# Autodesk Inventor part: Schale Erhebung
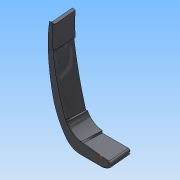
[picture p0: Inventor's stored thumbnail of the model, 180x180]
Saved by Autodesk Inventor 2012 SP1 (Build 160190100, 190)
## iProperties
Created: 2012-02
Part Number: Schale Erhebung
Material: S235JR+N ; 1.0116
Document SubType Name: Modeling
Designer: HUS
Density: 7.85 g/cm^3
Author: HUS
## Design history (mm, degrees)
workplane "Arbeitsebene1"
sketch "Skizze15"
  geometry: L1 (0, 112460.081)-(0, -18764.062) reference; L2 (-7625.161, 0)-(33492.439, 0) reference; L3 (233.258, 0)-(0, 0); L4 (-59.793, 88.26)-(221.355, 120.824); A1 r 97611.323 centre (27618.496, 93713.775) between (-29.671, 99.945) and (-29.671, 99.945); A2 r 1092.429 centre (-510.057, 901.526) between (582.372, 902.855) and (565.345, 1093.654); A3 r 72.871 centre (564.126, 1020.793) between (565.345, 1093.654) and (534.585, 1087.408); A4 r 2333.592 centre (-1751.218, 900.016) between (525.168, 386.483) and (582.372, 902.855); A5 r 2202.735 centre (-1667.311, 1026.612) between (397.261, 258.767) and (534.585, 1087.408); A6 r 276.67 centre (137.046, 355.352) between (379.784, 222.596) and (381.8, 226.351); A7 r 830.227 centre (-284.708, 569.184) between (382.626, 75.278) and (525.168, 386.483); A8 r 213.94 centre (196.739, 333.344) between (221.355, 120.824) and (397.261, 258.767); A9 r 185.828 centre (233.258, 185.828) between (233.258, 0) and (382.626, 75.278); A10 r 30 centre (-56.341, 58.459) between (-59.793, 88.26) and (-80.488, 40.656); A11 r 100 centre (0, 100) between (-80.488, 40.656) and (0, 0)
  constraints: 23 point on circle, 11 centre point, 9 tangent, 4 end point, 1 horizontal
  dimensions: "d197" = 100 radius of A11; "d198" = 30 radius of A10
sketch "Skizze16"
  geometry: L1 (233.259, 0)-(0, 0); L2 (-65.624, 24.545)-(-53.83, 36.782); L3 (-45.086, 70.419)-(238.074, 70.419); L4 (238.074, 70.419)-(238.074, 95.092); L5 (398.936, 202.433)-(418.507, 199.342); L6 (549.625, 827.221)-(534.585, 829.597); L7 (0, 0)-(233.259, 0); A1 r 1092.429 centre (-510.056, 901.526) between (582.372, 902.855) and (565.345, 1093.654); A2 r 72.871 centre (564.126, 1020.793) between (565.345, 1093.654) and (534.585, 1087.408); A3 r 17.417 centre (-48.326, 53.306) between (-45.086, 70.419) and (-53.83, 36.782); A4 r 194.102 centre (225.088, 288.759) between (238.074, 95.092) and (398.936, 202.433); A5 r 4086.087 centre (-3503.399, 1345.971) between (418.507, 199.342) and (549.625, 827.221); A6 r 2237.23 centre (-1698.928, 958.502) between (534.585, 829.597) and (534.585, 1087.408); A7 r 72.871 centre (564.126, 1020.793) between (549.625, 1092.207) and (534.585, 1087.408); A8 r 72.871 centre (564.126, 1020.793) between (565.345, 1093.654) and (549.625, 1092.207); A9 r 1092.429 centre (-510.056, 901.526) between (582.372, 902.855) and (565.345, 1093.654); A10 r 2333.592 centre (-1751.218, 900.016) between (525.168, 386.483) and (582.372, 902.855); A11 r 100 centre (0, 100) between (-65.624, 24.545) and (0, 0); A12 r 830.227 centre (-284.707, 569.184) between (382.627, 75.278) and (525.168, 386.483); A13 r 830.227 centre (-284.707, 569.184) between (382.627, 75.278) and (525.168, 386.483); A14 r 185.828 centre (233.258, 185.828) between (233.259, 0) and (382.627, 75.278)
  constraints: 29 point on circle, 14 centre point, 14 end point, 2 concentric, 2 parallel, 2 perpendicular, 2 tangent
workpoint "Arbeitspunkt2"
sketch "Skizze19"
  geometry: L1 (-39.856, 70.419)-(-250, 70.419); A1 r 44.453 centre (-39.856, 114.872) between (-39.856, 70.419) and (0, 95.186); 1 further point
  constraints: 2 end point, 2 point on circle, 1 centre point, 1 coincident, 1 horizontal, 1 tangent
feature "Erhebung6" sketch "Skizze19" dims "d204" = 0, "d205" = 90 deg, "d206" = 0, "d207" = 90 deg, "d208" = 0, "d209" = 90 deg
chamfer "Fase3" distance "d159" = 180; stored, may be unused: second distance "d160" = 2, angle "d161" = 30 deg
sketch "Skizze17"
  geometry: L1 (0, -2052.565)-(-250, -2052.565) reference; L2 (0, -2052.565)-(0, -2059.738) reference; L3 (0, -2850.001)-(0, -2059.738) reference; L4 (0, -2052.565)-(0, -2302.565); L5 (-167.543, -2052.565)-(0, -2052.565); L6 (-72.505, -2256.375)-(-167.543, -2052.565); L7 (0, -2302.565)-(21.782, -2302.565); A1 r 80 centre (0, -2222.565) between (-72.505, -2256.375) and (0, -2302.565); 3 further points
  constraints: 8 end point, 3 point on line, 2 point on circle, 2 tangent, 1 centre point, 1 collinear, 1 parallel
  dimensions: "d170" = 250 distance between parallel lines of L7 L1; "d171" = 80 radius of A1; "d172" = 65 deg angle of L7 L6
extrude "Extrusion11" cut sketch "Skizze17" stored distance "d165" = 0; taper "d166" = 0 deg
mirror "Spiegeln3"
node "Volumenkörper3"
node "Volumenkörpern"
node "Oberflächenkörpern"
node "Volumenkörper7"
node "Volumenkörper8"
